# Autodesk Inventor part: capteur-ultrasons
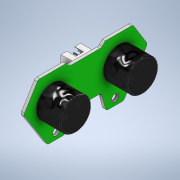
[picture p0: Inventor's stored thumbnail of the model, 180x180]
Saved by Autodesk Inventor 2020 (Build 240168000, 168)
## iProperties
Created: 2022-02
Part Number: capteur-ultrasons
Material: Générique
Document SubType Name: Modeling
Designer: bruno
Density: 1 g/cm^3
Appearance: Par défaut
Author: bruno
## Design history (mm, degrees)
sketch "Esquisse1"
  geometry: L1 (0, 0)-(20, 0); L2 (20, 0)-(20, 7.394); L3 (20, 8)-(0, 8); L4 (0, 6.839)-(0, 0); L5 (20.421, 8.436)-(22, 10.073); L6 (22, 10.073)-(22, 23.237); L7 (21.289, 24.513)-(10.803, 31.003); L8 (9.205, 30.99)-(-8.295, 19.772); L9 (-8.985, 18.51)-(-8.985, 11.49); L10 (-7.862, 10.038)-(-1.124, 8.291); L11 (-8.985, 15)-(6.493, 15); C1 r 1.75 at (-5.582, 15); A1 r 1.5 centre (10.014, 29.727) between (10.803, 31.003) and (9.205, 30.99); A2 r 1.5 centre (-7.485, 18.51) between (-8.295, 19.772) and (-8.985, 18.51); A3 r 1.5 centre (-7.485, 11.49) between (-8.985, 11.49) and (-7.862, 10.038); A4 r 1.5 centre (-1.5, 6.839) between (0, 6.839) and (-1.124, 8.291); A5 r 1.5 centre (20.5, 23.237) between (22, 23.237) and (21.289, 24.513); A6 r 1.5 centre (21.5, 7.394) between (20.421, 8.436) and (20, 7.394); 4 further points
  constraints: 22 end point, 13 point on line, 12 point on circle, 12 tangent, 7 centre point, 5 equal radius, 2 horizontal, 2 parallel, 2 vertical, 1 midpoint, 1 perpendicular
  dimensions: "d0" = 20 distance of L3.end L3.start; "d1" = 8 distance of L3.start L1.end; "d2" = 2 distance between parallel lines of L6 L2; "d3" = 31.5 distance from line of L1 point (10, 31.5); "d4" = 12 distance from line of L6 point (10, 31.5); "d6" = 9 distance of point (-8.985, 19.33) point (-8.985, 10.33); "d7" = 14 distance of L5.end point (22, 24.073); "d8" = 1.5 radius of A1; "d9" = 3.5 diameter of C1; "d37" = 15 distance from line of L1 C1.centre
extrude "Extrusion1" new body sketch "Esquisse1" distance "d10" = 1.5; taper "d11" = 0 deg
mirror "Symétrie1"
sketch "Esquisse2"
  geometry: L1 (-5, 19.693)-(5, 19.693); L2 (5, 19.693)-(5, 14.693); L3 (5, 14.693)-(-5, 14.693); L4 (-5, 14.693)-(-5, 19.693); L5 (0, 19.693)-(0, 20); L6 (7.394, 20)-(-7.394, 20) reference; L7 (-4.789, 19.493)-(4.822, 19.493); L8 (4.822, 19.493)-(4.822, 15.018); L9 (4.822, 15.018)-(-4.789, 15.018); L10 (-4.789, 15.018)-(-4.789, 19.493); 1 further point
  constraints: 18 end point, 4 parallel, 2 horizontal, 2 midpoint, 2 perpendicular, 1 vertical
  dimensions: "d12" = 10 distance of L2.end L3.end; "d13" = 5 distance of L1.end L2.end; "d14" = 0.2 distance between parallel lines of L7 L1
extrude "Extrusion2" join sketch "Esquisse2" distance "d15" = 6; taper "d16" = 0 deg
sketch "Esquisse3"
  geometry: L1 (-1.482, 7)-(-6.869, 7); L2 (-6.869, 7)-(-6.869, 3); L3 (-6.869, 3)-(-1.482, 3); L4 (-1.482, 3)-(-1.482, 7); L5 (0, 0)-(-6, 0) reference; L6 (0, 10)-(-6, 10) reference; 1 further point
  constraints: 8 end point, 2 parallel, 1 horizontal, 1 perpendicular
  dimensions: "d19" = 3 distance between parallel lines of L5 L3; "d20" = 3 distance between parallel lines of L6 L1
extrude "Extrusion3" cut sketch "Esquisse3" distance "d17" = 1; taper "d18" = 0 deg
sketch "Esquisse4" dims "d26" = 10
  geometry: L1 (-4.789, 19.493)-(-4.789, 15.018) reference; L2 (-4.789, 17.256)-(4.822, 17.256); L3 (4.822, 15.018)-(4.822, 19.493) reference; C1 r 0.37 at (-3.779, 17.256); C2 r 0.37 at (-1.379, 17.256); C3 r 0.37 at (1.021, 17.256); C4 r 0.37 at (3.421, 17.256); 1 further point
  constraints: 4 centre point, 2 end point, 2 midpoint, 1 horizontal, 1 point on line, 6 other
  dimensions: "d23" = 2.4 distance of C1.centre C2.centre
extrude "Extrusion4" join sketch "Esquisse4" distance "d28" = 6; taper "d29" = 0 deg
fillet "Congé1" dims "d30" = 0.2
sketch "Esquisse6"
  geometry: L1 (-10.073, 22)-(-23.237, 22) reference; C1 r 8 at (-17, 9); 1 further point
  constraints: 1 centre point
  dimensions: "d31" = 16 diameter of C1; "d32" = 13 distance from line of L1 C1.centre; "d33" = 17 horizontal distance of C1.centre point (0, 0)
extrude "Extrusion5" join sketch "Esquisse6" distance "d34" = 12; taper "d35" = 0 deg
fillet "Congé2" dims "d36" = 0.5
mirror "Symétrie2"
node "Solide1"
node "Plan de construction1"
